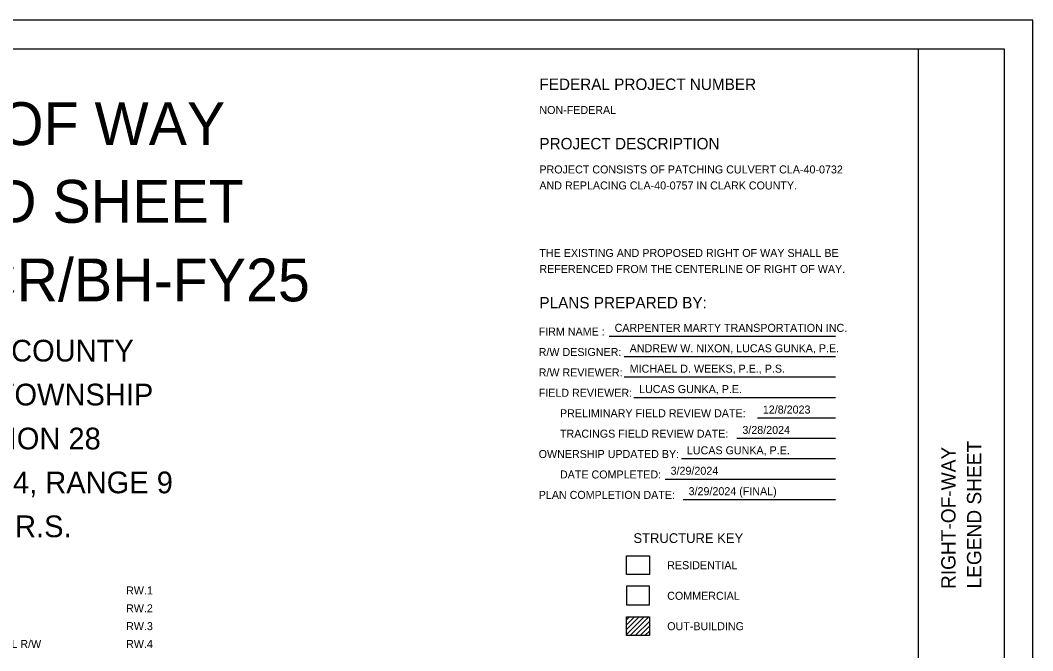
# Model space of a CAD drawing. Extents: x 0 to 34, y 0 to 22.
# Drawn here: x 16.3 to 34, y 10.97 to 22 of the extents above; entities that cross this region are included whole.
import ezdxf

# ---------------------------------------------------------------- set-up
doc = ezdxf.new("R2010")
doc.units = 0
for name, color, linetype in [('RW_X_Fee_WL', 7, 'Continuous'), ('SC_Shading1', 7, 'Continuous'), ('SH_Border', 7, 'Continuous'), ('SH_Cut_Line', 7, 'Continuous'), ('SH_Data', 7, 'Continuous'), ('SH_Text', 7, 'Continuous')]:
    doc.layers.add(name, color=color, linetype=linetype)

msp = doc.modelspace()

# ---------------------------------------------------------------- linework, layer by layer
at = {"layer": 'SC_Shading1'}
msp.add_lwpolyline([(26.9, 11.772), (27.297, 11.772), (27.297, 12.098), (26.9, 12.098)], close=True, dxfattribs=at)
at = {"layer": 'SH_Border'}
msp.add_line((32, 0.5), (32, 21.5), dxfattribs=at)
msp.add_lwpolyline([(1.5, 21.5), (33.5, 21.5), (33.5, 0.5), (1.5, 0.5)], close=True, dxfattribs=at)
at = {"layer": 'SH_Cut_Line'}
msp.add_lwpolyline([(0, 0), (34, 0), (34, 22), (0, 22)], close=True, dxfattribs=at)
at = {"layer": 'SH_Text'}
for p, q in [((26.594, 16.474), (30.553, 16.474)), ((26.858, 16.117), (30.553, 16.117)), ((26.858, 15.76), (30.553, 15.76)), ((27.023, 15.403), (30.553, 15.403)), ((29.186, 15.045), (30.553, 15.045)), ((28.828, 14.688), (30.553, 14.688)), ((27.859, 14.332), (30.553, 14.332)), ((27.573, 13.974), (30.553, 13.974)), ((27.888, 13.617), (30.553, 13.617)), ((26.9, 11.561), (26.901, 11.562)), ((26.9, 11.511), (26.951, 11.562)), ((26.9, 11.426), (27.036, 11.562)), ((26.9, 11.341), (27.121, 11.562)), ((26.9, 11.257), (27.205, 11.562)), ((26.964, 11.236), (27.29, 11.562)), ((27.049, 11.236), (27.297, 11.484)), ((27.134, 11.236), (27.297, 11.4)), ((26.9, 11.241), (26.904, 11.236)), ((27.218, 11.236), (27.297, 11.315))]:
    msp.add_line(p, q, dxfattribs=at)
for points in [[(26.9, 12.633), (27.297, 12.633), (27.297, 12.307), (26.9, 12.307)], [(26.9, 11.562), (27.297, 11.562), (27.297, 11.236), (26.9, 11.236)]]:
    msp.add_lwpolyline(points, close=True, dxfattribs=at)

# ---------------------------------------------------------------- texts
at = {"layer": 'RW_X_Fee_WL'}
for s, p in [('FEDERAL PROJECT NUMBER', (25.374, 20.78)), ('PROJECT DESCRIPTION', (25.374, 19.741))]:
    msp.add_text(s, height=0.2, dxfattribs=at).set_placement(p)
at = {"layer": 'SH_Data'}
for s, height, p in [('RIGHT OF WAY', 0.75, (12.527, 19.816)), ('LEGEND SHEET', 0.75, (12.458, 18.457)), (' CLA/MOT-CR/BH-FY25 ', 0.75, (10.439, 17.082)), ('      CLARK COUNTY     ', 0.38, (13.455, 16.03)), ('    BETHEL TOWNSHIP    ', 0.38, (13.203, 15.262)), ('               SECTION 28               ', 0.38, (12.623, 14.493)), ('  TOWNSHIP 4, RANGE 9  ', 0.38, (13.009, 13.725)), ('        B.M.R.S.       ', 0.38, (14.033, 12.957)), ('RW.1  ', 0.14, (18.148, 11.955)), ('RW.2  ', 0.14, (18.148, 11.643)), ('RW.3  ', 0.14, (18.148, 11.331)), ('SUMMARY OF ADDITIONAL R/W          ', 0.14, (13.803, 11.019)), ('RW.4  ', 0.14, (18.148, 11.019))]:
    msp.add_text(s, height=height, dxfattribs=at).set_placement(p)
for s, p in [('RIGHT-OF-WAY', (32.65, 12.05)), ('LEGEND SHEET', (33.1, 12.06))]:
    msp.add_text(s, height=0.25, rotation=90, dxfattribs=at).set_placement(p)
at = {"layer": 'SH_Text'}
for s, height, p in [('NON-FEDERAL', 0.14, (25.374, 20.36)), ('PROJECT CONSISTS OF PATCHING CULVERT CLA-40-0732', 0.14, (25.374, 19.32)), ('AND REPLACING CLA-40-0757 IN CLARK COUNTY.', 0.14, (25.374, 19.04)), ('THE EXISTING AND PROPOSED RIGHT OF WAY SHALL BE', 0.14, (25.374, 17.859)), ('REFERENCED FROM THE CENTERLINE OF RIGHT OF WAY.', 0.14, (25.374, 17.579)), ('PLANS PREPARED BY:', 0.2, (25.374, 16.959)), ('CARPENTER MARTY TRANSPORTATION INC.', 0.14, (26.689, 16.549)), ('FIRM NAME :', 0.14, (25.362, 16.484)), ('ANDREW W. NIXON, LUCAS GUNKA, P.E.', 0.14, (26.953, 16.192)), ('R/W DESIGNER:', 0.14, (25.362, 16.127)), ('MICHAEL D. WEEKS, P.E., P.S.', 0.14, (26.953, 15.835)), ('R/W REVIEWER:', 0.14, (25.362, 15.77)), ('LUCAS GUNKA, P.E.', 0.14, (27.117, 15.478)), ('FIELD REVIEWER:', 0.14, (25.362, 15.413)), ('12/8/2023', 0.14, (29.281, 15.12)), ('PRELIMINARY FIELD REVIEW DATE:', 0.14, (25.734, 15.055)), ('3/28/2024', 0.14, (28.923, 14.763)), ('TRACINGS FIELD REVIEW DATE:', 0.14, (25.734, 14.698)), ('LUCAS GUNKA, P.E.', 0.14, (27.953, 14.407)), ('OWNERSHIP UPDATED BY:', 0.14, (25.362, 14.342)), ('3/29/2024', 0.14, (27.668, 14.049)), ('DATE COMPLETED:', 0.14, (25.734, 13.984)), ('3/29/2024 (FINAL)', 0.14, (27.983, 13.692)), ('PLAN COMPLETION DATE:', 0.14, (25.362, 13.627)), ('STRUCTURE KEY', 0.17, (27.018, 12.856)), ('RESIDENTIAL', 0.14, (27.609, 12.397)), ('COMMERCIAL', 0.14, (27.609, 11.862)), ('OUT-BUILDING', 0.14, (27.609, 11.33))]:
    msp.add_text(s, height=height, dxfattribs=at).set_placement(p)

doc.saveas('drawing.dxf')
